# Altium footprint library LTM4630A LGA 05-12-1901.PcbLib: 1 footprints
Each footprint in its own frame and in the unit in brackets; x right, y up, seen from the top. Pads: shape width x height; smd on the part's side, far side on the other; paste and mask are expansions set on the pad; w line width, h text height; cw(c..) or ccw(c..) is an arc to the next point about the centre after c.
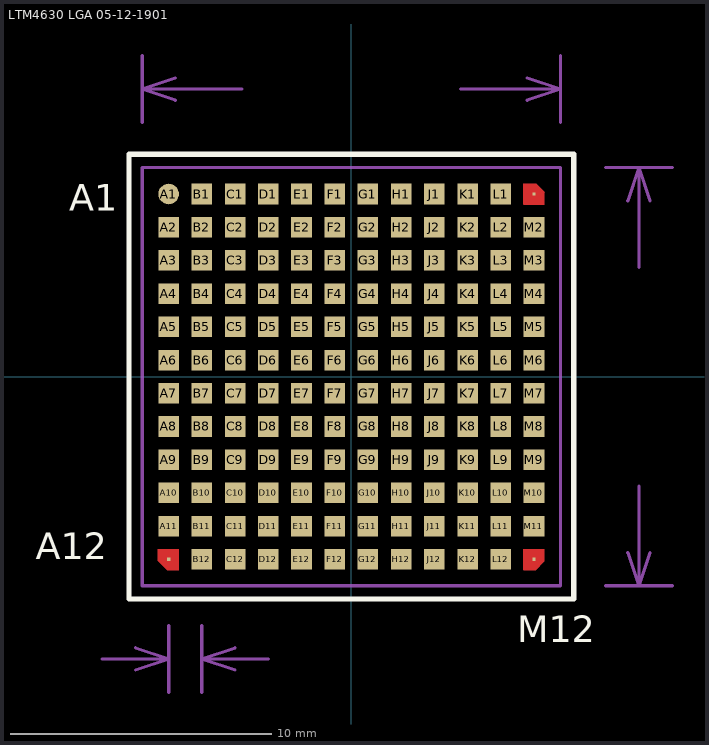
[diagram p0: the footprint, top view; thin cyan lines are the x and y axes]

## LTM4630 LGA 05-12-1901 [mil]
pads (144):
  round 31 smd paste-3.5 mask-3: A1(-275,275)
  rect 31x31 smd paste-3.5 mask-3: A2(-275,225) A3(-275,175) A4(-275,125) A5(-275,75) A6(-275,25) A7(-275,-25) A8(-275,-75) A9(-275,-125) A10(-275,-175) A11(-275,-225) B1(-225,275) B2(-225,225) B3(-225,175) B4(-225,125) B5(-225,75) B6(-225,25) B7(-225,-25) B8(-225,-75) B9(-225,-125) B10(-225,-175) B11(-225,-225) B12(-225,-275) C1(-175,275) C2(-175,225) C3(-175,175) C4(-175,125) C5(-175,75) C6(-175,25) C7(-175,-25) C8(-175,-75) C9(-175,-125) C10(-175,-175) C11(-175,-225) C12(-175,-275) D1(-125,275) D2(-125,225) D3(-125,175) D4(-125,125) D5(-125,75) D6(-125,25) D7(-125,-25) D8(-125,-75) D9(-125,-125) D10(-125,-175) D11(-125,-225) D12(-125,-275) E1(-75,275) E2(-75,225) E3(-75,175) E4(-75,125) E5(-75,75) E6(-75,25) E7(-75,-25) E8(-75,-75) E9(-75,-125) E10(-75,-175) E11(-75,-225) E12(-75,-275) F1(-25,275) F2(-25,225) F3(-25,175) F4(-25,125) F5(-25,75) F6(-25,25) F7(-25,-25) F8(-25,-75) F9(-25,-125) F10(-25,-175) F11(-25,-225) F12(-25,-275) G1(25,275) G2(25,225) G3(25,175) G4(25,125) G5(25,75) G6(25,25) G7(25,-25) G8(25,-75) G9(25,-125) G10(25,-175) G11(25,-225) G12(25,-275) H1(75,275) H2(75,225) H3(75,175) H4(75,125) H5(75,75) H6(75,25) H7(75,-25) H8(75,-75) H9(75,-125) H10(75,-175) H11(75,-225) H12(75,-275) J1(125,275) J2(125,225) J3(125,175) J4(125,125) J5(125,75) J6(125,25) J7(125,-25) J8(125,-75) J9(125,-125) J10(125,-175) J11(125,-225) J12(125,-275) K1(175,275) K2(175,225) K3(175,175) K4(175,125) K5(175,75) K6(175,25) K7(175,-25) K8(175,-75) K9(175,-125) K10(175,-175) K11(175,-225) K12(175,-275) L1(225,275) L2(225,225) L3(225,175) L4(225,125) L5(225,75) L6(225,25) L7(225,-25) L8(225,-75) L9(225,-125) L10(225,-175) L11(225,-225) L12(225,-275) M2(275,225) M3(275,175) M4(275,125) M5(275,75) M6(275,25) M7(275,-25) M8(275,-75) M9(275,-125) M10(275,-175) M11(275,-225)
  rect 5x5 smd paste-3.5 mask-3: A12(-275,-275) M1(275,275) M12(275,-275)
TopLayer:
  region: -290.5,-259.5 -259.5,-259.5 -259.5,-290.5 -277.5,-290.5 -290.5,-277.5
  region: 259.5,-259.5 259.5,-290.5 277.5,-290.5 290.5,-277.5 290.5,-259.5
  region: 259.5,290.5 259.5,259.5 290.5,259.5 290.5,277.5 277.5,290.5
  lines w0.39: -290.5,-277.5 -277.5,-290.5 -259.5,-290.5 -259.5,-259.5 -290.5,-259.5 -290.5,-277.5 ; 259.5,-290.5 277.5,-290.5 290.5,-277.5 290.5,-259.5 259.5,-259.5 259.5,-290.5 ; 259.5,259.5 290.5,259.5 290.5,277.5 277.5,290.5 259.5,290.5 259.5,259.5
TopOverlay:
  lines w8: -334.65,-334.65 334.65,-334.65 334.65,334.65 -334.65,334.65 -334.65,-334.65
  text "M12" at 250,-400 h40
  text "A1" at -425,250 h40
  text "A12" at -475,-275 h40
Mechanical16:
  lines w5: -375,-425 -275,-425 ; -325,-441.67 -275,-425 ; -325,-408.33 -275,-425 ; -314.96,383.07 -314.96,483.07 ; -275,-475 -275,-375 ; -264.96,416.4 -314.96,433.07 ; -264.96,449.74 -314.96,433.07 ; -225,-475 -225,-375 ; -175,-441.67 -225,-425 ; -175,-408.33 -225,-425 ; -164.95,433.07 -314.96,433.07 ; -125,-425 -225,-425 ; 164.95,433.07 314.96,433.07 ; 264.96,416.4 314.96,433.07 ; 264.96,449.74 314.96,433.07 ; 314.96,383.07 314.96,483.07 ; 383.07,-314.96 483.07,-314.96 ; 383.07,314.96 483.07,314.96 ; 416.4,-264.96 433.07,-314.96 ; 416.4,264.96 433.07,314.96 ; 433.07,-164.95 433.07,-314.96 ; 433.07,164.95 433.07,314.96 ; 449.74,-264.96 433.07,-314.96 ; 449.74,264.96 433.07,314.96 ; -314.96,-314.96 -314.96,314.96 314.96,314.96 314.96,-314.96 -314.96,-314.96
  text "1.27 (mm)" at -450.77,-544.97 h50
  text "16 (mm)" at 463.06,-154.95 h50
  text "16 (mm)" at -154.95,403.08 h50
